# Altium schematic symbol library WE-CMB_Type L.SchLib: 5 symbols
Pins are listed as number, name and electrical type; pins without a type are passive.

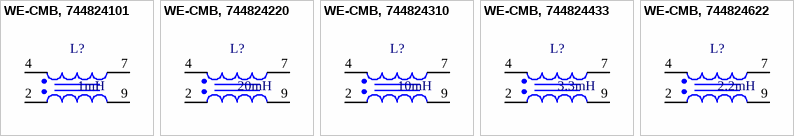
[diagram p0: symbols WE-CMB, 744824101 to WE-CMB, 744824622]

## WE-CMB, 744824101
designator L?, comment 1mH
WE-CMB Common Mode Power Line Choke, Type L, 1mH; PartNumber: 744824101
footprint WE-CMB_Type L
pins: 2, 4, 7, 9

## WE-CMB, 744824220
designator L?, comment 20mH
WE-CMB Common Mode Power Line Choke, Type L, 20mH; PartNumber: 744824220
footprint WE-CMB_Type L
pins: 2, 4, 7, 9

## WE-CMB, 744824310
designator L?, comment 10mH
WE-CMB Common Mode Power Line Choke, Type L, 10mH; PartNumber: 744824310
footprint WE-CMB_Type L
pins: 2, 4, 7, 9

## WE-CMB, 744824433
designator L?, comment 3.3mH
WE-CMB Common Mode Power Line Choke, Type L, 3.3mH; PartNumber: 744824433
footprint WE-CMB_Type L
pins: 2, 4, 7, 9

## WE-CMB, 744824622
designator L?, comment 2.2mH
WE-CMB Common Mode Power Line Choke, Type L, 2.2mH; PartNumber: 744824622
footprint WE-CMB_Type L
pins: 2, 4, 7, 9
